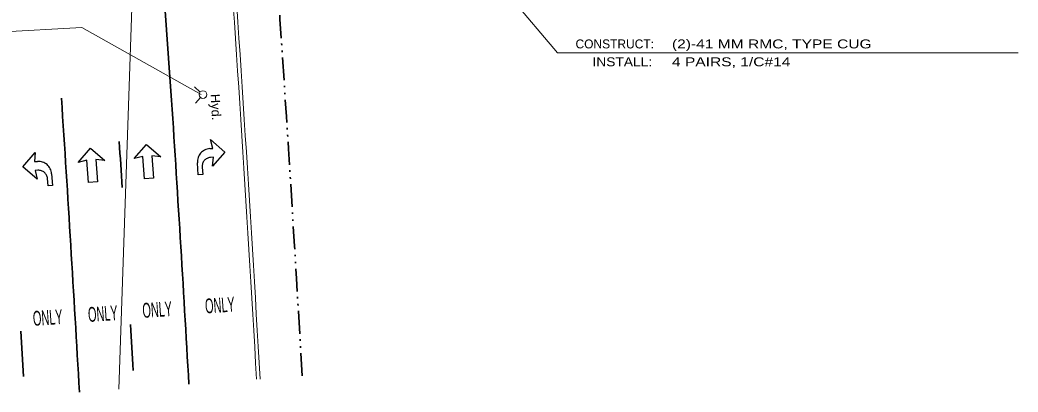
# Model space of a CAD drawing. Extents: x 168203 to 169864, y 223196 to 223870.
# Drawn here: x 168359.5 to 168425, y 223554.6 to 223579 of the extents above; entities that cross this region are included whole.
import ezdxf
from ezdxf.enums import TextEntityAlignment as Align

# ---------------------------------------------------------------- set-up
doc = ezdxf.new("R2010")
doc.units = 0
doc.header["$LTSCALE"] = 0.3
doc.linetypes.add('DASH_DOUBLE_DOT', pattern=[9.2, 5, -1.2, 0.3, -1.2, 0.3, -1.2])
doc.linetypes.add('LONG_DASH_SHORT_DASH', pattern=[9.9, 6, -1.2, 1.5, -1.2])
for name, color, linetype, lineweight in [('1', 7, 'Continuous', 13), ('10', 7, 'Continuous', 13), ('23', 7, 'Continuous', 25), ('36', 7, 'Continuous', 35)]:
    doc.layers.add(name, color=color, linetype=linetype, lineweight=lineweight)

msp = doc.modelspace()

# ---------------------------------------------------------------- linework, layer by layer
at = {"layer": '1', "linetype": 'DASH_DOUBLE_DOT', "lineweight": 35}
msp.add_arc((166159.6764, 223429.5467), 2221.9, 3.2524, 4.13349, dxfattribs=at)
at = {"layer": '1'}
for radius, start in [(2218.9, 3.25121), (2219.13, 3.2513)]:
    msp.add_arc((166159.6759, 223429.5469), radius, start, 4.13349, dxfattribs=at)
at = {"layer": '10'}
for p in [(168372.3015, 223603.4006), (168424.9661, 223576.8324)]:
    msp.add_line(p, (168394.7583, 223576.8324), dxfattribs=at)
at = {"layer": '23', "lineweight": 13}
for p, q in [((168367.4305, 223597.8004), (168365.9593, 223554.7364)), ((168353.5788, 223577.9352), (168363.5377, 223578.5022)), ((168363.5377, 223578.5022), (168371.3602, 223574.0988)), ((168371.304, 223574.2568), (168370.932, 223574.5907)), ((168371.3232, 223573.9037), (168370.9892, 223573.5317))]:
    msp.add_line(p, q, dxfattribs=at)
msp.add_circle((168371.4901, 223574.0898), 0.25, dxfattribs=at)
at = {"layer": '36'}
msp.add_line((168369.3895, 223574.3146), (168366.6354, 223612.4238), dxfattribs=at)
at = {"layer": '36', "linetype": 'LONG_DASH_SHORT_DASH', "lineweight": 25}
for points in [[(168366.9737, 223569.8797), (168367.7859, 223570.8185), (168368.7247, 223570.0063), (168368.134, 223570.0613), (168368.2395, 223568.6021), (168367.6558, 223568.5599), (168367.5503, 223570.0191)], [(168363.3011, 223569.6383), (168364.1133, 223570.5771), (168365.0521, 223569.7649), (168364.4614, 223569.8199), (168364.5669, 223568.3607), (168363.9832, 223568.3185), (168363.8777, 223569.7777)]]:
    msp.add_lwpolyline(points, close=True, dxfattribs=at)
for points in [[(168371.9356, 223570.5384), (168372.1302, 223570.5525), (168371.9908, 223571.1291), (168372.9296, 223570.3169), (168372.1174, 223569.3781), (168372.1724, 223569.9688), (168371.9778, 223569.9547)], [(168360.6642, 223569.1152), (168360.4696, 223569.1011), (168360.609, 223568.5245), (168359.6702, 223569.3367), (168360.4824, 223570.2755), (168360.4274, 223569.6848), (168360.622, 223569.6989)], [(168371.4363, 223569.3289), (168371.4715, 223568.8424), (168371.1797, 223568.8214), (168371.1234, 223569.5996)], [(168361.5608, 223568.8866), (168361.617, 223568.1084), (168361.3252, 223568.0873), (168361.29, 223568.5737)]]:
    msp.add_lwpolyline(points, dxfattribs=at)
at = {"layer": '36'}
for radius, start, end in [(2214.4501, 3.24946, 3.74834), (2207.2499, 3.24659, 3.74834), (2210.8499, 3.59029, 3.66829), (2210.8499, 3.27828, 3.35628), (2203.6498, 3.27829, 3.35628)]:
    msp.add_arc((166159.6765, 223429.5465), radius, start, end, dxfattribs=at)
at = {"layer": '36', "linetype": 'LONG_DASH_SHORT_DASH', "lineweight": 25}
for centre, radius, start, end in [((168371.999, 223569.6629), 0.8778, 94.13419, 184.13419), ((168372.0201, 223569.371), 0.5852, 94.13419, 184.13419), ((168360.6852, 223568.8233), 0.8778, 4.13419, 94.13419), ((168360.7063, 223568.5315), 0.5852, 4.13419, 94.13419)]:
    msp.add_arc(centre, radius, start, end, dxfattribs=at)

# ---------------------------------------------------------------- texts
at = {"layer": '10'}
msp.add_text('CONSTRUCT:', height=0.5873, dxfattribs=at).set_placement((168395.933, 223577.1216))
at = {"layer": '10', "width": 1.3}
for s, p in [('(2)-41 MM RMC, TYPE CUG              ', (168402.2583, 223577.1216)), ('4 PAIRS, 1/C#14                      ', (168402.2583, 223575.9469))]:
    msp.add_text(s, height=0.5873, dxfattribs=at).set_placement(p)
at = {"layer": '10', "width": 1.15}
msp.add_text('INSTALL:', height=0.5873, dxfattribs=at).set_placement((168400.9602, 223575.9469), align=Align.RIGHT)
at = {"layer": '23', "width": 1.05}
msp.add_text('Hyd.', height=0.6, rotation=273.098, dxfattribs=at).set_placement((168371.9893, 223574.1168))
at = {"layer": '36', "width": 0.55}
for p in [(168372.6296, 223559.7748), (168364.9499, 223559.2184), (168368.5186, 223559.4847), (168361.3361, 223558.9606)]:
    msp.add_text('ONLY', height=0.9715, rotation=3.898, dxfattribs=at).set_placement(p, align=Align.CENTER)

doc.saveas('drawing.dxf')
